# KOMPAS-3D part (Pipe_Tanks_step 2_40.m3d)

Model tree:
1. X Axis
2. Y Axis
3. Z Axis  (labels: Valve Dy 50; Pipe Dn 50)
     Òîëùèíà ñòåíêè 1 = 1

Referenced files in C:\Documents and Settings\kashirsky\Мои документы\Camtasia Studio\Pipelines3D\Tanks\: Tanks_step 2.a3d
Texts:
  Pipe Dn 50
  Steel ASTM A295
  Three Point Plane
  Plane at Angle
  Line and Point Plane
  Axis through Two Vertices
  Axis of Feature
  Axis of Conical Surface
  Axis through Edge
  Trim by Surface
  Trim by Sketch
  Feature with No History
  Intersection Axis of Two Planes
  Two Line Plane
  Line and Face Plane
  Bend by line
  Hole in sheet body
  Cut in sheet body
  Point in CM
  Linear Dimension from Line to Point
  Surface Finish Symbol
  Geometric Tolerance Symbol
  Leader #1
  Leader #2
  Leader #3
  Shape Deviations and Datum
  Node point number
  Mark of coordination axis
  Node point designation
  Mark/Reference designation with leader
  Mark/reference designation on line
  Mark/Reference designation without leader
  Valve Dy 50
  Plane of section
